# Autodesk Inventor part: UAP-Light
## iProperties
Author: Jan-Steinar
Shininess: 20.0
PropertySet Name: _Private Model Information
Created: 2001-01
Part Number: UAP-Light
Document SubType Name: Modeling
Designer: Jan-Steinar
Control State: 0
Master: False
Checked Out: False
PropertySet Name: Design Tracking Control
Density: 0.0
Volumn: 0.0
Area: 0.0
PropertySet Name: Model Information
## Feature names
1. Extrusion1
